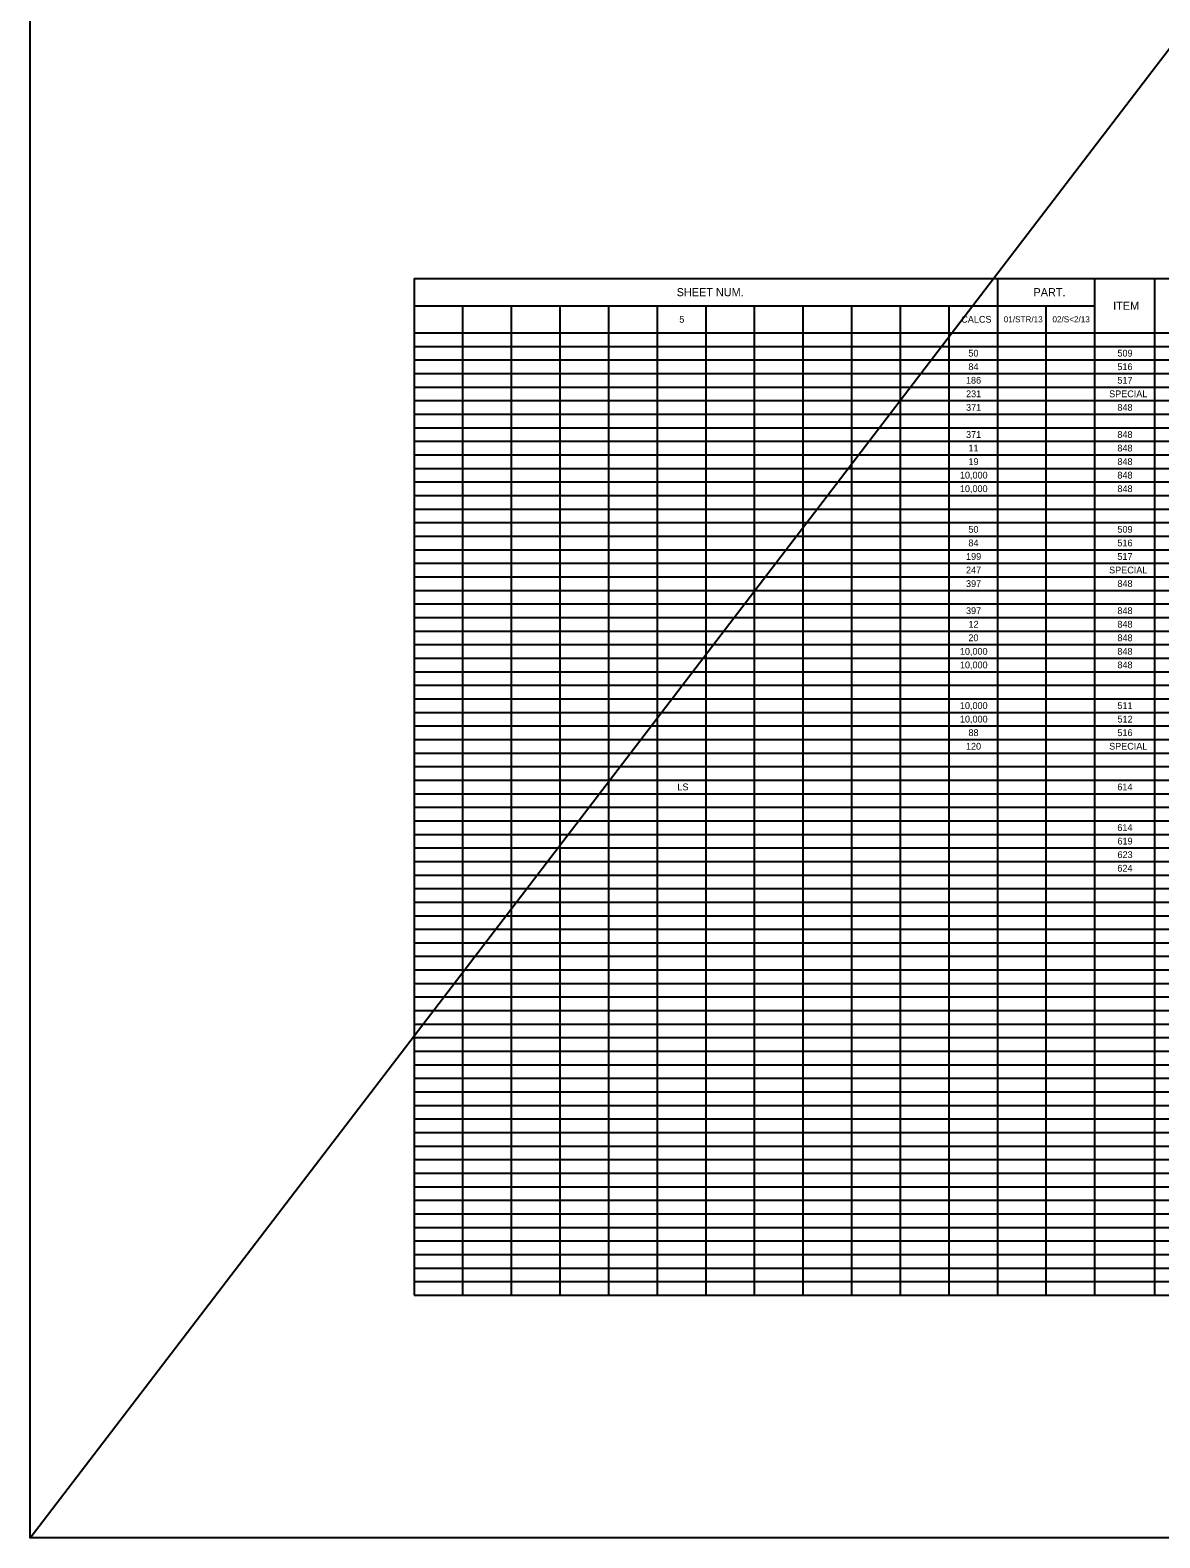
# Model space of a CAD drawing. Extents: x -53.2 to 35.8, y -26.4 to 35.9.
# Drawn here: x -53.16 to -29.81, y -26.4 to 4.75 of the extents above; entities that cross this region are included whole.
import ezdxf

# ---------------------------------------------------------------- set-up
doc = ezdxf.new("R2010")
doc.units = 0
for name, color, linetype in [('SC_Scratch1', 7, 'Continuous'), ('SH_Data', 7, 'Continuous'), ('SH_Text', 7, 'Continuous')]:
    doc.layers.add(name, color=color, linetype=linetype)

msp = doc.modelspace()

# ---------------------------------------------------------------- linework, layer by layer
at = {"layer": 'SC_Scratch1'}
msp.add_line((-53.157, -26.4), (-5.495, 35.892), dxfattribs=at)
msp.add_lwpolyline([(-53.157, 35.892), (-5.495, 35.892), (-5.495, -26.4), (-53.157, -26.4)], close=True, dxfattribs=at)
at = {"layer": 'SH_Data'}
for p, q in [((-45.223, -0.387), (-14.72, -0.387)), ((-45.223, -0.387), (-45.223, -21.387)), ((-33.167, -0.387), (-33.167, -21.387)), ((-31.157, -0.387), (-31.157, -21.387)), ((-29.922, -0.387), (-29.922, -21.387)), ((-45.223, -0.947), (-31.157, -0.947)), ((-44.218, -0.947), (-44.218, -21.387)), ((-43.214, -0.947), (-43.214, -21.387)), ((-42.209, -0.947), (-42.209, -21.387)), ((-41.204, -0.947), (-41.204, -21.387)), ((-40.2, -0.947), (-40.2, -21.387)), ((-39.195, -0.947), (-39.195, -21.387)), ((-38.19, -0.947), (-38.19, -21.387)), ((-37.186, -0.947), (-37.186, -21.387)), ((-36.181, -0.947), (-36.181, -21.387)), ((-35.176, -0.947), (-35.176, -21.387)), ((-34.171, -0.947), (-34.171, -21.387)), ((-32.162, -0.947), (-32.162, -21.387)), ((-45.223, -1.507), (-14.72, -1.507)), ((-45.223, -1.787), (-14.72, -1.787)), ((-45.223, -2.067), (-14.72, -2.067)), ((-45.223, -2.347), (-14.72, -2.347)), ((-45.223, -2.627), (-14.72, -2.627)), ((-45.223, -2.907), (-14.72, -2.907)), ((-45.223, -3.187), (-14.72, -3.187)), ((-45.223, -3.467), (-14.72, -3.467)), ((-45.223, -3.747), (-14.72, -3.747)), ((-45.223, -4.027), (-14.72, -4.027)), ((-45.223, -4.307), (-14.72, -4.307)), ((-45.223, -4.587), (-14.72, -4.587)), ((-45.223, -4.867), (-14.72, -4.867)), ((-45.223, -5.147), (-14.72, -5.147)), ((-45.223, -5.427), (-14.72, -5.427)), ((-45.223, -5.707), (-14.72, -5.707)), ((-45.223, -5.987), (-14.72, -5.987)), ((-45.223, -6.267), (-14.72, -6.267)), ((-45.223, -6.547), (-14.72, -6.547)), ((-45.223, -6.827), (-14.72, -6.827)), ((-45.223, -7.107), (-14.72, -7.107)), ((-45.223, -7.387), (-14.72, -7.387)), ((-45.223, -7.667), (-14.72, -7.667)), ((-45.223, -7.947), (-14.72, -7.947)), ((-45.223, -8.227), (-14.72, -8.227)), ((-45.223, -8.507), (-14.72, -8.507)), ((-45.223, -8.787), (-14.72, -8.787)), ((-45.223, -9.067), (-14.72, -9.067)), ((-45.223, -9.347), (-14.72, -9.347)), ((-45.223, -9.627), (-14.72, -9.627)), ((-45.223, -9.907), (-14.72, -9.907)), ((-45.223, -10.187), (-14.72, -10.187)), ((-45.223, -10.467), (-14.72, -10.467)), ((-45.223, -10.747), (-14.72, -10.747)), ((-45.223, -11.027), (-14.72, -11.027)), ((-45.223, -11.307), (-14.72, -11.307)), ((-45.223, -11.587), (-14.72, -11.587)), ((-45.223, -11.867), (-14.72, -11.867)), ((-45.223, -12.147), (-14.72, -12.147)), ((-45.223, -12.427), (-14.72, -12.427)), ((-45.223, -12.707), (-14.72, -12.707)), ((-45.223, -12.987), (-14.72, -12.987)), ((-45.223, -13.267), (-14.72, -13.267)), ((-45.223, -13.547), (-14.72, -13.547)), ((-45.223, -13.827), (-14.72, -13.827)), ((-45.223, -14.107), (-14.72, -14.107)), ((-45.223, -14.387), (-14.72, -14.387)), ((-45.223, -14.667), (-14.72, -14.667)), ((-45.223, -14.947), (-14.72, -14.947)), ((-45.223, -15.227), (-14.72, -15.227)), ((-45.223, -15.507), (-14.72, -15.507)), ((-45.223, -15.787), (-14.72, -15.787)), ((-45.223, -16.067), (-14.72, -16.067)), ((-45.223, -16.347), (-14.72, -16.347)), ((-45.223, -16.627), (-14.72, -16.627)), ((-45.223, -16.907), (-14.72, -16.907)), ((-45.223, -17.187), (-14.72, -17.187)), ((-45.223, -17.467), (-14.72, -17.467)), ((-45.223, -17.747), (-14.72, -17.747)), ((-45.223, -18.027), (-14.72, -18.027)), ((-45.223, -18.307), (-14.72, -18.307)), ((-45.223, -18.587), (-14.72, -18.587)), ((-45.223, -18.867), (-14.72, -18.867)), ((-45.223, -19.147), (-14.72, -19.147)), ((-45.223, -19.427), (-14.72, -19.427)), ((-45.223, -19.707), (-14.72, -19.707)), ((-45.223, -19.987), (-14.72, -19.987)), ((-45.223, -20.267), (-14.72, -20.267)), ((-45.223, -20.547), (-14.72, -20.547)), ((-45.223, -20.827), (-14.72, -20.827)), ((-45.223, -21.107), (-14.72, -21.107)), ((-45.223, -21.387), (-14.72, -21.387))]:
    msp.add_line(p, q, dxfattribs=at)

# ---------------------------------------------------------------- texts
at = {"layer": 'SH_Text'}
for s, height, p in [('SHEET NUM.', 0.168, (-39.795, -0.751)), ('PART.', 0.168, (-32.42, -0.751)), ('ITEM', 0.168, (-30.774, -1.031)), ('5', 0.14, (-39.741, -1.297)), ('CALCS', 0.14, (-33.913, -1.297)), ('01/STR/13', 0.126, (-33.035, -1.29)), ('02/S<2/13', 0.126, (-32.029, -1.29)), ('50', 0.14, (-33.766, -1.997)), ('509', 0.14, (-30.685, -1.997)), ('84', 0.14, (-33.766, -2.277)), ('516', 0.14, (-30.686, -2.277)), ('186', 0.14, (-33.816, -2.557)), ('517', 0.14, (-30.686, -2.557)), ('231', 0.14, (-33.814, -2.837)), ('SPECIAL', 0.14, (-30.857, -2.837)), ('371', 0.14, (-33.814, -3.117)), ('848', 0.14, (-30.686, -3.117)), ('371', 0.14, (-33.814, -3.677)), ('848', 0.14, (-30.686, -3.677)), ('11', 0.14, (-33.764, -3.957)), ('848', 0.14, (-30.686, -3.957)), ('19', 0.14, (-33.764, -4.237)), ('848', 0.14, (-30.686, -4.237)), ('10,000', 0.14, (-33.941, -4.517)), ('10,000', 0.14, (-33.941, -4.797)), ('848', 0.14, (-30.686, -4.517)), ('848', 0.14, (-30.686, -4.797)), ('50', 0.14, (-33.766, -5.637)), ('509', 0.14, (-30.685, -5.637)), ('84', 0.14, (-33.766, -5.917)), ('516', 0.14, (-30.686, -5.917)), ('199', 0.14, (-33.814, -6.197)), ('517', 0.14, (-30.686, -6.197)), ('247', 0.14, (-33.815, -6.477)), ('SPECIAL', 0.14, (-30.857, -6.477)), ('397', 0.14, (-33.815, -6.757)), ('848', 0.14, (-30.686, -6.757)), ('397', 0.14, (-33.815, -7.317)), ('12', 0.14, (-33.763, -7.597)), ('848', 0.14, (-30.686, -7.317)), ('848', 0.14, (-30.686, -7.597)), ('20', 0.14, (-33.766, -7.877)), ('848', 0.14, (-30.686, -7.877)), ('10,000', 0.14, (-33.941, -8.157)), ('848', 0.14, (-30.686, -8.157)), ('10,000', 0.14, (-33.941, -8.437)), ('848', 0.14, (-30.686, -8.437)), ('10,000', 0.14, (-33.941, -9.277)), ('511', 0.14, (-30.685, -9.277)), ('10,000', 0.14, (-33.941, -9.557)), ('512', 0.14, (-30.684, -9.557)), ('88', 0.14, (-33.765, -9.837)), ('516', 0.14, (-30.686, -9.837)), ('120', 0.14, (-33.816, -10.117)), ('SPECIAL', 0.14, (-30.857, -10.117)), ('LS', 0.14, (-39.78, -10.957)), ('614', 0.14, (-30.687, -10.957)), ('614', 0.14, (-30.687, -11.797)), ('619', 0.14, (-30.685, -12.077)), ('623', 0.14, (-30.684, -12.357)), ('624', 0.14, (-30.687, -12.637))]:
    msp.add_text(s, height=height, dxfattribs=at).set_placement(p)

doc.saveas('drawing.dxf')
